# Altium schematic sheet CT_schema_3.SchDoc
size 357 x 214 mm
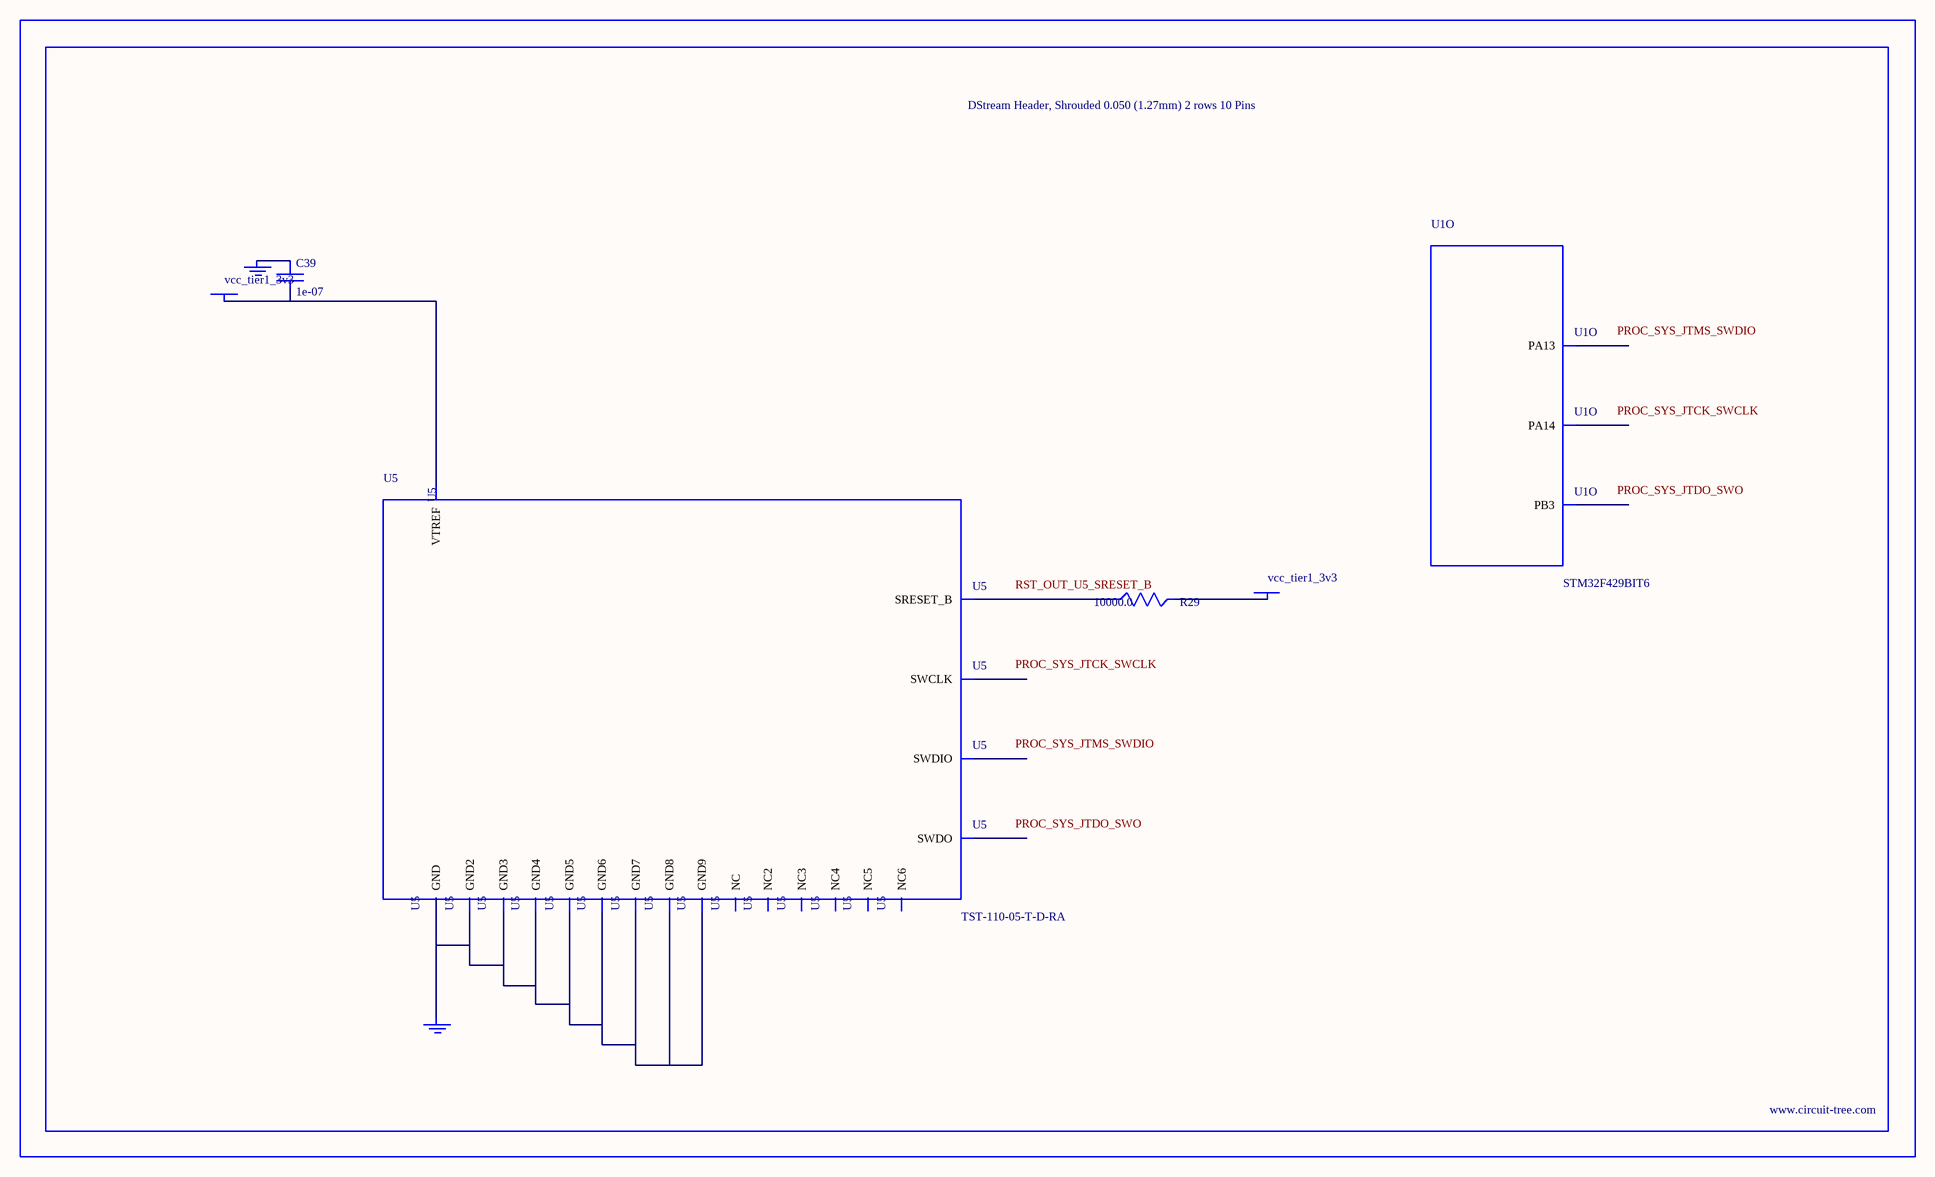
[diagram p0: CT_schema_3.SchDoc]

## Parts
BORDER2  (no value)
C39  1e-07  [C0402]
GND_INSTANCE_2_0  (no value)
GND_INSTANCE_2_1  (no value)
POWER_INSTANCE_2_0  vcc_tier1_3v3
POWER_INSTANCE_2_1  vcc_tier1_3v3
R29  10000.0  [R0603]
U1  STM32F429BIT6  [LQFP208]  (part O of 16)
U5  TST-110-05-T-D-RA  [TST-110-05-T-D-RA]

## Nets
NetC39_1: C39.1 GND_INSTANCE_2_0.0(GND)
NetC39_2: C39.2 POWER_INSTANCE_2_0.0(PWR) U5.1(VTREF)
NetGND_INSTANCE_2_1_0: GND_INSTANCE_2_1.0(GND) U5.4(GND) U5.6(GND2) U5.8(GND3) U5.10(GND4) U5.12(GND5) U5.14(GND6) U5.16(GND7) U5.18(GND8) U5.20(GND9)
NetPOWER_INSTANCE_2_1_0: POWER_INSTANCE_2_1.0(PWR) R29.2
NetR29_1: R29.1 U5.15(SRESET_B)

Not connected (* = marked no-connect by the designer): U1 147(PA13) 159(PA14) 192(PB3); U5 2(NC) 3(NC2) 5(NC3) 7(SWDIO) 9(SWCLK) 11(NC4) 13(SWDO) 17(NC5) 19(NC6)

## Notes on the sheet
- Labels drawn without touching a wire or pin: PROC_SYS_JTCK_SWCLK, PROC_SYS_JTDO_SWO, PROC_SYS_JTMS_SWDIO, RST_OUT_U5_SRESET_B

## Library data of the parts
BORDER2 = BORDER_PAGE2
C39 = C0402C104K3RACTU
GND_INSTANCE_2_0 GND_INSTANCE_2_1 = GND
POWER_INSTANCE_2_0 POWER_INSTANCE_2_1 = PWR
R29 = RC0603JR-0710KL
